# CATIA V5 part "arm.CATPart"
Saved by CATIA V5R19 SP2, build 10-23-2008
Part number: arm
Bounding box of the stored display mesh (mm): x -1674.402 to 1983, y -599.019 to 599.163, z 0 to 719.537
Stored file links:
  C:\BEHROOZ\catia learning\tarh haye mashin\hb\arm.CATPart
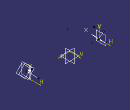
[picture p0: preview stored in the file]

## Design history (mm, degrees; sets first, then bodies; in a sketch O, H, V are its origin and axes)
Body1 (main body)
  DatumSurface1
  Plane1: stored without definition
  ThickSurface1: Surface DatumSurface1, TopOffset 1, BotOffset 0
  Sketch1 on Plane1, origin (1983, 0, 0), H (0, 1, 0), V (0, 0, 1)
    projected curve E1 from edge [face of ThickSurface1 | face of ThickSurface1]
    projected curve E2 from edge [face of ThickSurface1 | face of ThickSurface1]
    projected curve E3 from edge [face of ThickSurface1 | face of ThickSurface1]
    projected curve E4 from edge [face of ThickSurface1 | face of ThickSurface1]
    projected curve E5 from edge [face of ThickSurface1 | face of ThickSurface1]
    projected line E6 (-2.1622, 387.9184) -> (2.1623, 387.9181) from edge [face of ThickSurface1 | face of ThickSurface1]
    projected curve E7 from edge [face of ThickSurface1 | face of ThickSurface1]
    projected curve E8 from edge [face of ThickSurface1 | face of ThickSurface1]
    projected curve E9 from edge [face of ThickSurface1 | face of ThickSurface1]
    projected curve E10 from edge [face of ThickSurface1 | face of ThickSurface1]
    projected curve E11 from edge [face of ThickSurface1 | face of ThickSurface1]
    projected curve E12 from edge [face of ThickSurface1 | face of ThickSurface1]
    projected curve E13 from edge [face of ThickSurface1 | face of ThickSurface1]
    projected curve E14 from edge [face of ThickSurface1 | face of ThickSurface1]
    projected curve E15 from edge [face of ThickSurface1 | face of ThickSurface1]
    projected arc E16 centre (149.622, 204.4603) radius 192.1306 from (273.8144, 351.0564) to (247.6306, 369.7131) ccw from edge [face of ThickSurface1 | face of ThickSurface1]
    projected arc E17 centre (220.183, 323.4204) radius 53.818 from (247.6306, 369.7131) to (220.6889, 377.2361) ccw from edge [face of ThickSurface1 | face of ThickSurface1]
    projected curve E18 from edge [face of ThickSurface1 | face of ThickSurface1]
    projected curve E19 from edge [face of ThickSurface1 | face of ThickSurface1]
    projected line E20 (75.5393, 362.9035) -> (69.7952, 358.5533) from edge [face of ThickSurface1 | face of ThickSurface1]
    projected curve E21 from edge [face of ThickSurface1 | face of ThickSurface1]
    projected curve E22 from edge [face of ThickSurface1 | face of ThickSurface1]
    projected curve E23 from edge [face of ThickSurface1 | face of ThickSurface1]
    projected curve E24 from edge [face of ThickSurface1 | face of ThickSurface1]
    projected line E25 (-69.7948, 358.5538) -> (-75.539, 362.9041) from edge [face of ThickSurface1 | face of ThickSurface1]
    projected curve E26 from edge [face of ThickSurface1 | face of ThickSurface1]
    projected curve E27 from edge [face of ThickSurface1 | face of ThickSurface1]
    projected arc E28 centre (-220.1827, 323.42) radius 53.8183 from (-220.6893, 377.236) to (-247.6307, 369.7128) ccw from edge [face of ThickSurface1 | face of ThickSurface1]
    projected arc E29 centre (-149.6212, 204.4606) radius 192.1305 from (-247.6307, 369.7128) to (-273.8142, 351.0561) ccw from edge [face of ThickSurface1 | face of ThickSurface1]
    projected curve E30 from edge [face of ThickSurface1 | face of ThickSurface1]
    projected curve E31 from edge [face of ThickSurface1 | face of ThickSurface1]
    projected curve E32 from edge [face of ThickSurface1 | face of ThickSurface1]
    projected curve E33 from edge [face of ThickSurface1 | face of ThickSurface1]
    projected curve E34 from edge [face of ThickSurface1 | face of ThickSurface1]
    projected line E35 (-77.6319, 272.8549) -> (-72.1406, 276.9425) from edge [face of ThickSurface1 | face of ThickSurface1]
    projected arc E36 centre (-66.7492, 269.6957) radius 9.0324 from (-66.7277, 278.7281) to (-72.1406, 276.9425) ccw from edge [face of ThickSurface1 | face of ThickSurface1]
    projected curve E37 from edge [face of ThickSurface1 | face of ThickSurface1]
    projected curve E38 from edge [face of ThickSurface1 | face of ThickSurface1]
    projected arc E39 centre (66.7492, 269.6965) radius 9.0326 from (72.1407, 276.9435) to (66.7277, 278.729) ccw from edge [face of ThickSurface1 | face of ThickSurface1]
    projected line E40 (72.1407, 276.9435) -> (77.632, 272.8559) from edge [face of ThickSurface1 | face of ThickSurface1]
    projected curve E41 from edge [face of ThickSurface1 | face of ThickSurface1]
    projected curve E42 from edge [face of ThickSurface1 | face of ThickSurface1]
    projected curve E43 from edge [face of ThickSurface1 | face of ThickSurface1]
    projected curve E44 from edge [face of ThickSurface1 | face of ThickSurface1]
    ellipse A1 centre (0, 368.3348) semi-axes 37.3284, 15.248 rotation 358.346
  Pocket1: profile Sketch1, direction (-1, 0, 0), length 20, opposite side length -243
  Plane2: stored without definition
  Sketch2 on Plane2, origin (1983, 0, 0), H (0, 1, 0), V (0, 0, 1)
    construction line L1 (0, 341.3672) -> (0, 371.8739)
    ellipse A1 centre (0, 356.6206) semi-axes 34.6341, 12.2312 rotation 0
    line L2 (-20.6052, 347.8467) -> (-20.6052, 365.3944)
    construction line L3 (6.8684, 367.4937) -> (6.8684, 347.8467)
    line L4 (-16.0195, 365.3944) -> (-16.0195, 358.6085)
    line L5 (-20.6052, 365.3944) -> (-16.0195, 365.3944)
    line L6 (-11.6191, 365.3944) -> (-6.8684, 365.3944)
    line L7 (-6.8684, 365.3944) -> (-12.5578, 356.6206)
    line L8 (-16.0195, 358.6085) -> (-11.6191, 365.3944)
    line L9 (-2.2929, 365.3944) -> (2.2929, 365.3944)
    line L10 (-2.2929, 365.3944) -> (-2.2929, 347.8467)
    line L11 (-2.2929, 347.8467) -> (2.2929, 347.8467)
    line L12 (2.2929, 347.8467) -> (2.2929, 365.3944)
    line L13 (11.4439, 347.8467) -> (6.8684, 347.8467)
    line L14 (6.8684, 347.8467) -> (11.4439, 365.3944)
    line L15 (11.4439, 365.3944) -> (16.0297, 365.3944)
    line L16 (16.0297, 365.3944) -> (20.6052, 347.8467)
    line L17 (20.6052, 347.8467) -> (16.0297, 347.8467)
    line L18 (16.0297, 347.8467) -> (13.7368, 356.6401)
    line L19 (11.4439, 347.8467) -> (13.7368, 356.6401)
    construction line L20 (-6.8684, 365.3944) -> (-6.8684, 347.8467)
    axis line L21 (-6.8684, 356.6206) -> (-12.5578, 356.6206)
    line L22 (-6.8684, 347.8467) -> (-12.5578, 356.6206)
    line L23 (-11.6191, 347.8467) -> (-6.8684, 347.8467)
    line L24 (-16.0195, 354.6327) -> (-11.6191, 347.8467)
    line L25 (-16.0195, 347.8467) -> (-16.0195, 354.6327)
    line L26 (-20.6052, 347.8467) -> (-16.0195, 347.8467)
  DatumSurface2
  Plane3: stored without definition
  ThickSurface2: Surface DatumSurface2, TopOffset 1, BotOffset 0
  Sketch3 on Plane3, origin (0, 0, 187.3531), H (1, 0, 0), V (0, 1, 0)
    line L1 (1923.9407, 344.5241) -> (1923.9407, -219.7086)
    point P2 (1923.9407, -219.7086)
  Plane4: stored without definition
  Plane5: type OffsetPt, RefPlane Plane4, RefPoint Sketch3.P2
  Plane6: type Angle, RefPlane Plane5, Direction Sketch3, Angle 42
  Plane7: type Offset, RefPlane Plane6, Offset 177
  Rotate1: ToTransfor Sketch2, Axis Sketch3, Angle 42
  Plane8: stored without definition
  Pocket2: profile Rotate1, length 70
  Sketch4 on Plane8, origin (1983, 0, 0), H (0, 1, 0), V (0, 0, 1)
    projected curve E1 from Sketch2.A1
    ellipse A1 centre (0, 356.6206) semi-axes 36.1807, 16.6503 rotation 0
    projected line E2 (20.6052, 347.8467) -> (16.0297, 365.3944) from Sketch2.L16
    projected line E3 (16.0297, 347.8467) -> (20.6052, 347.8467) from Sketch2.L17
    projected line E4 (13.7368, 356.6401) -> (16.0297, 347.8467) from Sketch2.L18
    projected line E5 (11.4439, 347.8467) -> (13.7368, 356.6401) from Sketch2.L19
    projected line E6 (6.8684, 347.8467) -> (11.4439, 347.8467) from Sketch2.L13
    projected line E7 (11.4439, 365.3944) -> (6.8684, 347.8467) from Sketch2.L14
    projected line E8 (16.0297, 365.3944) -> (11.4439, 365.3944) from Sketch2.L15
    projected line E9 (2.2929, 365.3944) -> (-2.2929, 365.3944) from Sketch2.L9
    projected line E10 (-6.8684, 365.3944) -> (-11.6191, 365.3944) from Sketch2.L6
    projected line E11 (-16.0195, 365.3944) -> (-20.6052, 365.3944) from Sketch2.L5
    projected line E12 (-16.0195, 358.6085) -> (-16.0195, 365.3944) from Sketch2.L4
    projected line E13 (-11.6191, 365.3944) -> (-16.0195, 358.6085) from Sketch2.L8
    projected line E14 (-12.5578, 356.6206) -> (-6.8684, 365.3944) from Sketch2.L7
    projected line E15 (-2.2929, 365.3944) -> (-2.2929, 347.8467) from Sketch2.L10
    projected line E16 (2.2929, 347.8467) -> (2.2929, 365.3944) from Sketch2.L12
    projected line E17 (-2.2929, 347.8467) -> (2.2929, 347.8467) from Sketch2.L11
    projected line E18 (-11.6191, 347.8467) -> (-6.8684, 347.8467) from Sketch2.L23
    projected line E19 (-20.6052, 347.8467) -> (-16.0195, 347.8467) from Sketch2.L26
    projected line E20 (-16.0195, 347.8467) -> (-16.0195, 354.6327) from Sketch2.L25
    projected line E21 (-16.0195, 354.6327) -> (-11.6191, 347.8467) from Sketch2.L24
    projected line E22 (-6.8684, 347.8467) -> (-12.5578, 356.6206) from Sketch2.L22
    projected line E23 (-20.6052, 365.3944) -> (-20.6052, 347.8467) from Sketch2.L2
    line L1 (1166.3764, 993.0937) -> (-733.2099, 993.0937)
    line L2 (-733.2099, 993.0937) -> (-733.2099, -169.8552)
    line L3 (-733.2099, -169.8552) -> (1166.3764, -169.8552)
    line L4 (1166.3764, -169.8552) -> (1166.3764, 993.0937)
  Rotate2: Axis Sketch3, Angle 42, ToTransfor Sketch4
  Pocket3: profile Rotate2, length 70, mirrored extent
  DatumSurface3
  ThickSurface3: Surface DatumSurface3, TopOffset 1, BotOffset 0
  DatumSurface4
  ThickSurface4: Surface DatumSurface4, TopOffset 1, BotOffset 0
  DatumSurface5 to DatumSurface8
  ThickSurface5: Surface DatumSurface8, TopOffset 1, BotOffset 0
  DatumSurface9
  ThickSurface6: Surface DatumSurface9, TopOffset 1, BotOffset 0
  Plane9: stored without definition
  Plane10: stored without definition
  Plane11: type Offset, RefPlane Plane9, Offset -2238
  Sketch5 on Plane10, origin (-1447, 0, 0), H (0, 1, 0), V (0, 0, 1)
    line L1 (0, 0) -> (341.2889, 0)
  Sketch6 on Plane11, origin (-1544, 0, 0), H (0, 1, 0), V (0, 0, 1)
    ellipse A1 centre (0, 635.5747) semi-axes 34.6341, 12.2312 rotation 180
    ellipse A2 centre (0, 635.5747) semi-axes 36.1807, 16.6503 rotation 180
    line L1 (-20.6052, 626.8009) -> (-16.0297, 644.3485)
    line L2 (-16.0297, 644.3485) -> (-11.4439, 644.3485)
    line L3 (-11.4439, 644.3485) -> (-6.8684, 626.8009)
    line L4 (-6.8684, 626.8009) -> (-11.4439, 626.8009)
    line L5 (-11.4439, 626.8009) -> (-13.7368, 635.5943)
    line L6 (-13.7368, 635.5943) -> (-16.0297, 626.8009)
    line L7 (-16.0297, 626.8009) -> (-20.6052, 626.8009)
    line L8 (-2.2929, 644.3485) -> (2.2929, 644.3485)
    line L9 (2.2929, 644.3485) -> (2.2929, 626.8009)
    line L10 (2.2929, 626.8009) -> (-2.2929, 626.8009)
    line L11 (-2.2929, 626.8009) -> (-2.2929, 644.3485)
    line L12 (6.8684, 644.3485) -> (11.6191, 644.3485)
    line L13 (11.6191, 644.3485) -> (16.0195, 637.5626)
    line L14 (16.0195, 637.5626) -> (16.0195, 644.3485)
    line L15 (16.0195, 644.3485) -> (20.6052, 644.3485)
    line L16 (20.6052, 644.3485) -> (20.6052, 626.8009)
    line L17 (20.6052, 626.8009) -> (16.0195, 626.8009)
    line L18 (16.0195, 626.8009) -> (16.0195, 633.5868)
    line L19 (16.0195, 633.5868) -> (11.6191, 626.8009)
    line L20 (11.6191, 626.8009) -> (6.8684, 626.8009)
    line L21 (6.8684, 626.8009) -> (12.5578, 635.5747)
    line L22 (12.5578, 635.5747) -> (6.8684, 644.3485)
    line L23 (-1120.2729, 1404.1737) -> (1166.3764, 1386.5273)
    line L24 (-1120.2729, -169.8552) -> (-1120.2729, 1404.1737)
    line L25 (1166.3764, -169.8552) -> (-1120.2729, -169.8552)
    line L26 (1166.3764, 1386.5273) -> (1166.3764, -169.8552)
  Rotate3: Axis Sketch5, Angle 46, ToTransfor Sketch6
  Plane12: type Angle, RefPlane Plane11, Direction Sketch5, Angle 42
  Point1: type OnPlane, Support Plane12, H 0, V 0, Direction (0, 1, 0)
  Line1: type Normal, RefPoint vertex of Sketch5, RefSkin Plane12, Start 0, End -306
  Translate1: ToTransfor Rotate3, Direction Line1, Length -399
  Pocket4: profile Translate1, length 70, opposite side length 714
